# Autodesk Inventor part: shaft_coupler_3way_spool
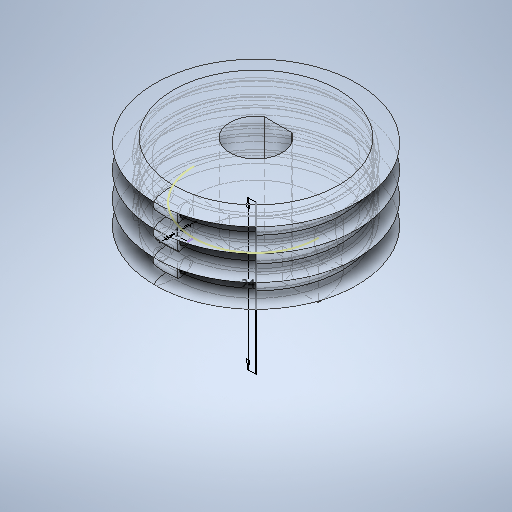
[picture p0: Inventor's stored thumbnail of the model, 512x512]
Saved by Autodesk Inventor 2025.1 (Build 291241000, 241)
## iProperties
Created: 2025-03
Part Number: shaft_coupler_3way_spool
Material: Genérico
Document SubType Name: Modeling
Designer: Usuario
Density: 1 g/cm^3
Appearance: Valor por defecto
Author: Usuario
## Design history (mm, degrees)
sketch "Boceto1"
  geometry: L1 (-0.079, -4.178)-(-0.079, -3.578); L2 (-0.079, -3.578)-(2.2, -3.578); L3 (-0.079, -3.578)-(-2.2, -3.578); C1 r 10 at (0, 0); A1 r 4.2 centre (0, 0) between (2.2, -3.578) and (-2.2, -3.578); 1 further point
  constraints: 6 end point, 2 centre point, 2 coincident, 2 point on circle, 1 perpendicular, 1 point on line, 1 vertical
  dimensions: "d0" = 8.4 diameter of A1; "d1" = 20 diameter of C1; "d2" = 0.6 distance of L1.start L1.end
extrude "Extrusión1" new body sketch "Boceto1" stored distance "d3" = 8; taper "d4" = 0 deg
sketch "Boceto2"
  geometry: L1 (-2.2, 3.578)-(2.2, 3.578) reference; L2 (2.2, 3.578)-(-2.2, 3.578); L3 (-4.2, 0)-(-10, 0); L4 (4.05, 0)-(10, 0); A1 r 10 centre (0, 0) between (10, 0) and (-10, 0); A2 r 4.2 centre (0, 0) between (4.2, 0) and (2.2, 3.578); A3 r 4.2 centre (0, 0) between (-2.2, 3.578) and (-4.2, 0); 2 further points
  constraints: 6 end point, 6 point on circle, 3 centre point, 2 coincident, 1 collinear, 1 horizontal, 1 point on line
extrude "Extrusión2" join sketch "Boceto2" distance "d5" = 5; taper "d6" = 0 deg
node "Plano de trabajo1"
mirror "Simetría1"
node "Plano de trabajo2"
sketch "Boceto3"
  geometry: L1 (0, 0)-(5, 0) reference; L2 (0, 0)-(0, 2.9); L3 (0, 5.8)-(0, 0) reference; L4 (0, 2.9)-(2.5, 2.9); C1 r 1.5 at (2.5, 2.9); 1 further point
  constraints: 4 end point, 1 centre point, 1 coincident, 1 midpoint, 1 perpendicular
  dimensions: "d7" = 2.9 distance of L1.start L2.end (derived); "d8" = 2.5 distance of L2.end L4.end; "d9" = 3 diameter of C1
extrude "screw1" cut sketch "Boceto3" distance "d10" = 9; taper "d11" = 0 deg
node "Plano de trabajo3"
sketch "Boceto4"
  geometry: C1 r 1.5 at (2.5, 2.9) reference; C2 r 1.5 at (2.5, 2.9); C3 r 3.75 at (2.5, 2.9); 1 further point
  constraints: 2 centre point, 2 coincident, 1 concentric
  dimensions: "d15" = 7.5 diameter of C3
extrude "Extrusión4" cut sketch "Boceto4" distance "d13" = 9; taper "d14" = 0 deg
node "Plano de trabajo5"
sketch "Boceto7"
  geometry: L1 (0, -10)-(0, -11); A1 r 10 centre (0, 0) between (-10, 0) and (10, 0) reference; 1 further point
  constraints: 2 end point, 1 point on circle, 1 vertical
  dimensions: "d29" = 1 distance of L1.start L1.end
node "Plano de trabajo6"
feature "Rosca5" dims "d47" = 6, "d48" = 0
sketch "Boceto12"
  geometry: L1 (-4, 10)-(20, 10)
  constraints: 2 end point, 1 horizontal
  dimensions: "d53" = 24 distance of L1.start L1.end
feature "Engrosado3" dims "d58" = 5, "d59" = 5
node "double_spool"
sketch "Boceto15"
  geometry: L1 (0, 4)-(0, -9) reference; L2 (0, -9)-(0, -2.5); L3 (0, -2.5)-(1, -2.5); L4 (0, -9)-(1, -9); L5 (0, 4)-(1, 4); L6 (0, -2.5)-(0, 0.75); L7 (0, -2.5)-(0, -5.75); L8 (1, 4)-(3.275, 4); L9 (1, -9)-(3.275, -9); L10 (3.275, -9)-(3.275, -8.25); L11 (0, -9)-(0, -6.375); L12 (0, -6.375)-(7.528, -6.375); L13 (0, 1.375)-(1.8, 1.375); A1 r 6.5 centre (1, -2.5) between (1.1, 3.999) and (1, 4); 17 further points; 4 other entities
  constraints: 24 end point, 7 point on line, 6 horizontal, 3 perpendicular, 3 symmetric about line, 2 coincident, 2 midpoint, 2 point on circle, 2 vertical, 1 centre point, 28 other
  dimensions: "d68" = 3.25 distance of L2.end L6.end; "d69" = 3.25 distance of L2.end L7.end; "d88" = 0.75 distance of L9.end L10.end; "d89" = 2.625 distance of L1.end L11.end; "d91" = 1.8 distance of L13.start L13.end
revolve "cable_guide" sketch "Boceto15" stored, may be unused: angle "d70" = 360 deg
node "Plano de trabajo12"
node "Plano de trabajo11"
sketch "Boceto17"
  geometry: L1 (-6.385, 11.79)-(-6.385, 12.99); L2 (-9, -13.275)-(-9, 13.275) reference; L3 (-9, 13.275)-(-6.375, 13.275); L4 (-7.5, -13.275)-(-7.5, 13.275) reference; L5 (-6.375, 13.275)-(-6.375, 13.775); L6 (-7.688, 13.275)-(-7.688, 13.775); L7 (-5.062, 13.275)-(-5.062, 13.775); L8 (-9, 13.275)-(-2.5, 13.275); L9 (4, -13.275)-(4, 13.275) reference; L10 (-2.5, 13.275)-(-2.5, 16.897); L11 (2.688, 13.275)-(2.688, 13.775); L12 (0.062, 13.275)-(0.062, 13.775); L13 (-9, 13.275)-(-4.667, 13.275); L14 (-9, 13.275)-(-4.43, 13.275); L15 (-4.43, 13.275)-(-4.43, 17.501); L16 (-1.172, 13.275)-(-1.172, 13.775); L17 (-3.798, 13.275)-(-3.798, 13.775); 16 further points; 7 other entities
  constraints: 28 end point, 12 symmetric about line, 8 vertical, 3 coincident, 3 horizontal, 3 perpendicular, 3 point on line, 2 midpoint, 28 other
  dimensions: "d94" = 1.2 distance of L1.end L1.start; "d96" = 2.625 distance of L2.end L3.end; "d97" = 0.5 distance of L5.start L5.end; "d100" = 4.57 distance of L2.end L14.end
revolve "cable_cover" sketch "Boceto17" stored, may be unused: angle "d85" = 270 deg
node "Plano de trabajo13"
sketch "Boceto18" dims "d103" = 2
  geometry: L1 (-6.515, -13.275)-(-6.515, 13.275) reference; L2 (-6.515, 13.275)-(-1.265, 13.275); L3 (-6.515, 13.275)-(-3.89, 13.275); L4 (-6.515, 13.275)-(-3.89, 13.275); L5 (-5.202, 14.275)-(-5.015, 13.275); L6 (-2.579, 14.252)-(-2.765, 13.275); 14 further points; 3 other entities
  constraints: 10 end point, 3 point on line, 2 coincident, 1 collinear, 1 horizontal, 1 midpoint, 1 vertical alignment, 15 other
revolve "cable_fix" sketch "Boceto18" stored, may be unused: angle "d105" = 15 deg
node "Plano de trabajo14"
mirror "Simetría2"
node "Plano de trabajo17"
  node "Plano de trabajo16"
mirror "Simetría3"
feature "Engrosado4" dims "d106" = 1, "d107" = 1
node "Sólido1"
other parameters: "d12" = 6, "d30" = 90 deg, "d60" = 90 deg, "d65" = 12.8, "d77" = 45 deg
